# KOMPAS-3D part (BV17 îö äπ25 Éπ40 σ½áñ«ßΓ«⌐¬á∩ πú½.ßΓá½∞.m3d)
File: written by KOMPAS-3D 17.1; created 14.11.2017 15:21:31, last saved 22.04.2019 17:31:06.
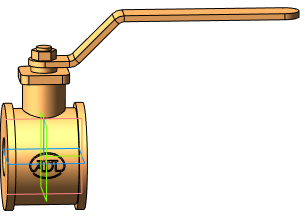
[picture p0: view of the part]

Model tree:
1. Операция без истории:2  (labels: Сталь 20  ГОСТ 1050-2013)

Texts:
  Толщина листового тела
  Глубина освобождения сгиба
  Ширина освобождения сгиба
